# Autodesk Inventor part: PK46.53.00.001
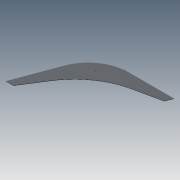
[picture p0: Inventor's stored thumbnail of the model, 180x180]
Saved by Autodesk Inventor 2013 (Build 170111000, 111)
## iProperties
Created: 2005-03
Part Number: PK46.53.00.001
Material: Steel, Mild
Document SubType Name: Modeling
Designer: HKostja
Manufacturer: Standard
Standards Organization: Custom
Density: 7.86 g/cm^3
Mass: 4881.47 g
Surface Area: 3207.19 cm^2
Volume: 621.052 cm^3
Author: HKostja
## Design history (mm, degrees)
sketch "Эскиз1"
  geometry: L1 (264.331, 0)-(690, 0); L2 (690, 0)-(665.652, -65.629); L3 (-170, -646.916)-(-240, -646.916); L4 (-240, -646.916)-(-91.941, -247.826); L5 (-170, -646.916)-(125.21, -180); L6 (665.652, -65.629)-(125.21, -180); L7 (0, 0)-(559.054, -803.691); L8 (-32.608, -429.61)-(-170, -646.916); L9 (414.127, -118.858)-(665.652, -65.629); C1 r 3.5 at (105, -150); A1 r 700 centre (559.054, -803.691) between (414.127, -118.858) and (-32.608, -429.61); A2 r 380 centre (264.331, -380) between (264.331, 0) and (-91.941, -247.826)
  constraints: 18 end point, 6 tangent, 5 point on line, 4 point on circle, 3 centre point, 2 collinear, 2 equal length, 2 parallel, 1 horizontal, 1 other
  dimensions: "d0" = 690 distance of L7.start L1.end; "d1" = 70 distance of L3.start L3.end; "d3" = 240 horizontal distance of L7.start L3.end; "d5" = 700 radius of A1; "d6" = 380 radius of A2; "d9" = 180 distance from line of L1 L5.end; "d11" = 7 diameter of C1; "d12" = 150 distance from line of L1 C1.centre; "d13" = 585 horizontal distance of L1.end C1.centre
extrude "Выдавливание1" new body sketch "Эскиз1" distance "d7" = 4; taper "d8" = 0 deg
body "Solid1"
